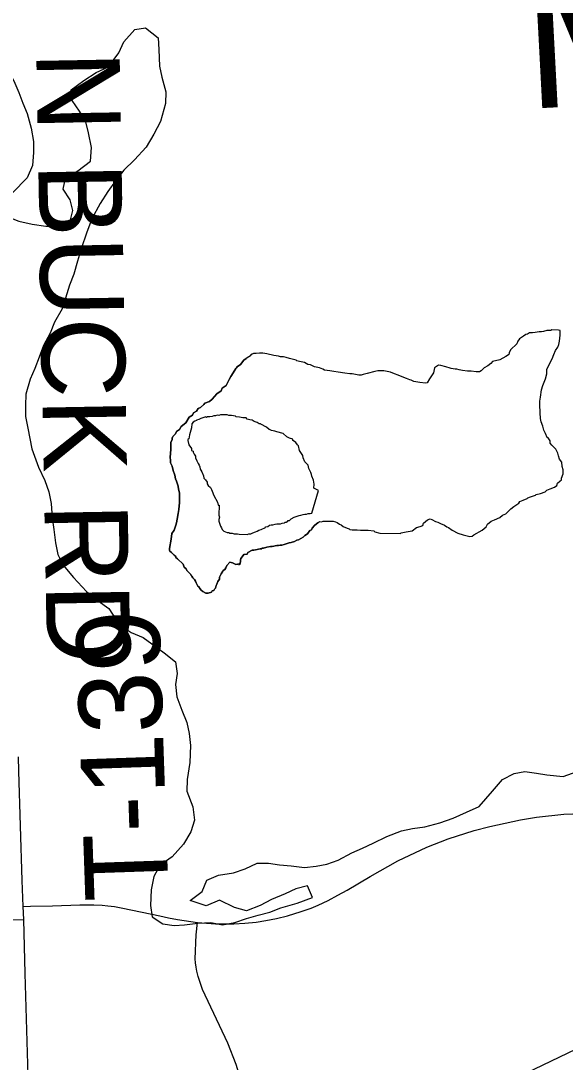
# Model space of a CAD drawing. Extents: x 63.4 to 97.4, y 0.4 to 22.4.
# Drawn here: x 69.568 to 69.939, y 18.671 to 19.381 of the extents above; entities that cross this region are included whole.
import ezdxf

# ---------------------------------------------------------------- set-up
doc = ezdxf.new("R2010")
doc.units = 0
for name, color, linetype in [('GM_X_Minor_River', 7, 'Continuous'), ('GM_X_Minor_River_Text', 7, 'Continuous'), ('GM_X_State_Route', 7, 'Continuous'), ('GM_X_Township_Road', 7, 'Continuous'), ('GM_X_Township_Road_Text', 7, 'Continuous')]:
    doc.layers.add(name, color=color, linetype=linetype)

msp = doc.modelspace()

# ---------------------------------------------------------------- linework, layer by layer
at = {"layer": 'GM_X_Minor_River'}
for points in [[(69.55778, 19.38334), (69.55402, 19.3761), (69.55179, 19.36658), (69.55449, 19.35861), (69.55834, 19.34912), (69.56332, 19.3404), (69.56678, 19.33243), (69.56947, 19.32522), (69.57255, 19.31801), (69.57526, 19.30813), (69.57682, 19.29901), (69.57686, 19.29141), (69.57615, 19.28266), (69.57239, 19.27427), (69.56258, 19.26396), (69.55313, 19.25555), (69.55924, 19.24759), (69.56685, 19.24459), (69.57597, 19.24273), (69.58509, 19.24125)], [(69.58509, 19.24125), (69.59459, 19.24129), (69.60178, 19.24475), (69.60364, 19.25198), (69.60171, 19.2592), (69.59711, 19.2664), (69.59859, 19.27401), (69.60692, 19.279), (69.61562, 19.2855), (69.61633, 19.29501), (69.61438, 19.30489), (69.61244, 19.31249), (69.60823, 19.31969), (69.60325, 19.3269), (69.60246, 19.33412), (69.61116, 19.34062), (69.61948, 19.34599), (69.62781, 19.34983), (69.63498, 19.35937), (69.63836, 19.36699), (69.64591, 19.37539), (69.65311, 19.37657), (69.66188, 19.36976), (69.6623, 19.36178), (69.66274, 19.35037), (69.6643, 19.34277), (69.66701, 19.3329), (69.66667, 19.32491), (69.66331, 19.31273), (69.6588, 19.30396), (69.65353, 19.29519), (69.64561, 19.28641), (69.63843, 19.27953), (69.63277, 19.27227), (69.62749, 19.26502), (69.62222, 19.25663), (69.61658, 19.24634), (69.61283, 19.23644), (69.60947, 19.22653), (69.60686, 19.21739), (69.60425, 19.20864), (69.60125, 19.20102), (69.59863, 19.19226), (69.59639, 19.18502), (69.59113, 19.17587), (69.58813, 19.16825), (69.58362, 19.15987), (69.58062, 19.15187), (69.57762, 19.14425), (69.57462, 19.13701), (69.57164, 19.12673), (69.5713, 19.11912), (69.57134, 19.11151), (69.5729, 19.10354), (69.57563, 19.08948), (69.58025, 19.07695), (69.58447, 19.06785), (69.58717, 19.06025), (69.58873, 19.05228), (69.58954, 19.04239), (69.59072, 19.03441), (69.5919, 19.0253), (69.59346, 19.01732), (69.59692, 19.01011), (69.60417, 19.00178), (69.61295, 18.99231), (69.62096, 18.98589), (69.6282, 18.9806), (69.63509, 18.9696), (69.64347, 18.96432), (69.65146, 18.96093), (69.66594, 18.95036), (69.67357, 18.94431), (69.67475, 18.93633), (69.67365, 18.92872), (69.67445, 18.92036), (69.67791, 18.91125), (69.68138, 18.9029), (69.68293, 18.8953), (69.68373, 18.88732), (69.68341, 18.87553), (69.68158, 18.86412), (69.68123, 18.85613), (69.68547, 18.84551), (69.68665, 18.83639), (69.68404, 18.82839), (69.67914, 18.82), (69.67122, 18.81122), (69.66289, 18.80548), (69.65876, 18.79785), (69.6569, 18.78872), (69.65658, 18.77807), (69.65776, 18.77047), (69.665, 18.76556), (69.6726, 18.76446), (69.67981, 18.76487), (69.68891, 18.76606), (69.69764, 18.76648), (69.70563, 18.76499), (69.71397, 18.76655), (69.72193, 18.76925)], [(69.93029, 19.1508), (69.93147, 19.15382), (69.93265, 19.15646), (69.9342, 19.15872), (69.93498, 19.16061), (69.93539, 19.16289), (69.93584, 19.16706), (69.93588, 19.1701), (69.93475, 19.17049), (69.9302, 19.17056), (69.92943, 19.17019), (69.92678, 19.17023), (69.9245, 19.1695), (69.92297, 19.16914), (69.92146, 19.16916), (69.9188, 19.16882), (69.9169, 19.16847), (69.915, 19.16849), (69.91347, 19.16776), (69.91233, 19.16739), (69.9108, 19.16627), (69.90812, 19.16441), (69.90696, 19.16291), (69.90617, 19.16102), (69.90194, 19.1569), (69.90115, 19.15501), (69.90076, 19.15388), (69.89999, 19.15313), (69.89884, 19.15239), (69.89464, 19.15016), (69.88969, 19.14909), (69.88853, 19.14759), (69.88661, 19.1461), (69.88394, 19.14462), (69.88201, 19.14274), (69.88087, 19.142), (69.87859, 19.14203), (69.87518, 19.14246), (69.87253, 19.1425), (69.86912, 19.14293), (69.86685, 19.14334), (69.86534, 19.14374), (69.86421, 19.14376), (69.86156, 19.14417), (69.86081, 19.14456), (69.85778, 19.14537), (69.85438, 19.14618), (69.85287, 19.14658), (69.85019, 19.14472), (69.84938, 19.14131), (69.84667, 19.13716), (69.84511, 19.13453), (69.84397, 19.13416), (69.84018, 19.1346), (69.83602, 19.13542), (69.83414, 19.1362), (69.83339, 19.13659), (69.83112, 19.13738), (69.82811, 19.13857), (69.82547, 19.13975), (69.82283, 19.14054), (69.82019, 19.14172), (69.81565, 19.14255), (69.81148, 19.1426), (69.80958, 19.14225), (69.80425, 19.14081), (69.80159, 19.14008), (69.80006, 19.13973), (69.79855, 19.13975), (69.79401, 19.14057), (69.79249, 19.14059), (69.78909, 19.14102), (69.78455, 19.14184), (69.78152, 19.14227), (69.77887, 19.14269), (69.77509, 19.14312), (69.77396, 19.14389), (69.7717, 19.14469), (69.7683, 19.14549), (69.76566, 19.14667), (69.76377, 19.14708), (69.76151, 19.14825), (69.75811, 19.14906), (69.75622, 19.14946), (69.75585, 19.14985), (69.75131, 19.15105), (69.74905, 19.15184), (69.74716, 19.15225), (69.74526, 19.15228), (69.74375, 19.15268), (69.74073, 19.1531), (69.73581, 19.15431), (69.73317, 19.15473), (69.73089, 19.15476), (69.72861, 19.15441), (69.72672, 19.15444), (69.72595, 19.15407), (69.7248, 19.15333), (69.7248, 19.15295), (69.72365, 19.1522), (69.72174, 19.15109)], [(69.72174, 19.15109), (69.7202, 19.14997), (69.71788, 19.14697), (69.71559, 19.14548), (69.7152, 19.14472), (69.71481, 19.14435), (69.71404, 19.14322), (69.71132, 19.1387), (69.71015, 19.13682), (69.7082, 19.13266), (69.70551, 19.1308), (69.70473, 19.12891), (69.70167, 19.12706), (69.69858, 19.1233), (69.69666, 19.12181), (69.69361, 19.12071), (69.69284, 19.11959), (69.69053, 19.11772), (69.68901, 19.11698), (69.68784, 19.1151), (69.68593, 19.11398), (69.68515, 19.11248), (69.68285, 19.11099), (69.68052, 19.10722), (69.67745, 19.10461), (69.67628, 19.10272), (69.67437, 19.10123), (69.67359, 19.09972), (69.67205, 19.09822), (69.67165, 19.09709), (69.67127, 19.09709), (69.67126, 19.09595), (69.67046, 19.09369), (69.6704, 19.08913), (69.66994, 19.08381), (69.67029, 19.08153), (69.67026, 19.08001), (69.67137, 19.07772), (69.67208, 19.07467), (69.67317, 19.07161), (69.67352, 19.06895), (69.67425, 19.06742), (69.67534, 19.06398), (69.67569, 19.06208), (69.67641, 19.05941), (69.67631, 19.05295), (69.67586, 19.04802), (69.67545, 19.04536), (69.67463, 19.04158), (69.67421, 19.03892), (69.67381, 19.03741), (69.67263, 19.03401), (69.67107, 19.03175), (69.67064, 19.02796), (69.66941, 19.02151), (69.66939, 19.02037), (69.66976, 19.01961), (69.67089, 19.01883), (69.67275, 19.01691), (69.67388, 19.01613), (69.67387, 19.01537), (69.67499, 19.01459), (69.67873, 19.01074), (69.67946, 19.00884), (69.68096, 19.00767), (69.68132, 19.00653), (69.68394, 19.00383), (69.68431, 19.00307), (69.68468, 19.00268), (69.68542, 19.00153), (69.68654, 19.00037), (69.68728, 18.99923), (69.68765, 18.99808), (69.68875, 18.99579), (69.6895, 18.9954), (69.68987, 18.99463), (69.69024, 18.99425), (69.69099, 18.99309), (69.69211, 18.99232), (69.69437, 18.99115), (69.69589, 18.99112), (69.69817, 18.99185), (69.69856, 18.99261), (69.69971, 18.99297), (69.7001, 18.99373), (69.70087, 18.99448), (69.70127, 18.99637), (69.70166, 18.99712), (69.70245, 18.99901), (69.70361, 19.00051), (69.70363, 19.00203), (69.7048, 19.0043), (69.70596, 19.00618), (69.70597, 19.00656), (69.70712, 19.0073), (69.70789, 19.00843), (69.70867, 19.00994), (69.7106, 19.01219), (69.71249, 19.01179), (69.71475, 19.01062), (69.7175, 19.01103)], [(69.71703, 19.01096), (69.71475, 19.01062), (69.71249, 19.01179), (69.7106, 19.01219), (69.70867, 19.00994), (69.70789, 19.00843), (69.70712, 19.0073), (69.70597, 19.00656), (69.70596, 19.00618), (69.7048, 19.0043), (69.70363, 19.00203), (69.70361, 19.00051), (69.70245, 18.99901), (69.70166, 18.99712), (69.70127, 18.99637), (69.70087, 18.99448), (69.7001, 18.99373), (69.69971, 18.99297), (69.69856, 18.99261), (69.69817, 18.99185), (69.69589, 18.99112), (69.69437, 18.99115), (69.69211, 18.99232), (69.69099, 18.99309), (69.69024, 18.99425), (69.68987, 18.99463), (69.6895, 18.9954), (69.68875, 18.99579), (69.68765, 18.99808), (69.68728, 18.99923), (69.68654, 19.00037), (69.68542, 19.00153), (69.68468, 19.00268), (69.68431, 19.00307), (69.68394, 19.00383), (69.68132, 19.00653), (69.68096, 19.00767), (69.67946, 19.00884), (69.67873, 19.01074), (69.67499, 19.01459), (69.67387, 19.01537), (69.67388, 19.01613), (69.67275, 19.01691), (69.67089, 19.01883), (69.66976, 19.01961), (69.66939, 19.02037), (69.66941, 19.02151), (69.67064, 19.02796), (69.67107, 19.03175), (69.67263, 19.03401), (69.67381, 19.03741), (69.67421, 19.03892), (69.67463, 19.04158), (69.67545, 19.04536), (69.67586, 19.04802), (69.67631, 19.05295), (69.67641, 19.05941), (69.67569, 19.06208), (69.67534, 19.06398), (69.67425, 19.06742), (69.67352, 19.06895), (69.67317, 19.07161), (69.67208, 19.07467), (69.67137, 19.07772), (69.67026, 19.08001), (69.67029, 19.08153), (69.66994, 19.08381), (69.6704, 19.08913), (69.67046, 19.09369), (69.67126, 19.09595), (69.67127, 19.09709), (69.67165, 19.09709), (69.67205, 19.09822), (69.67359, 19.09972), (69.67437, 19.10123), (69.67628, 19.10272), (69.67745, 19.10461), (69.68052, 19.10722), (69.68285, 19.11099), (69.68515, 19.11248), (69.68593, 19.11398), (69.68784, 19.1151), (69.68901, 19.11698), (69.69053, 19.11772), (69.69284, 19.11959), (69.69361, 19.12071), (69.69666, 19.12181), (69.69858, 19.1233), (69.70167, 19.12706), (69.70473, 19.12891), (69.70551, 19.1308), (69.7082, 19.13266), (69.71015, 19.13682), (69.71132, 19.1387), (69.71404, 19.14322), (69.71481, 19.14435), (69.7152, 19.14472), (69.71559, 19.14548), (69.71788, 19.14697), (69.7202, 19.14997), (69.72174, 19.15109)], [(69.77053, 19.03908), (69.77168, 19.03982), (69.7732, 19.0398), (69.77434, 19.04017), (69.77623, 19.04014), (69.78116, 19.04007), (69.78267, 19.03967), (69.78381, 19.03927), (69.78531, 19.03811), (69.78644, 19.03772), (69.78794, 19.03655), (69.79057, 19.03538), (69.79208, 19.03498), (69.79246, 19.03459), (69.79397, 19.03419), (69.79738, 19.03414), (69.79966, 19.03411), (69.80496, 19.03404), (69.80875, 19.0336), (69.80949, 19.03283), (69.8129, 19.03202), (69.82692, 19.03183), (69.82731, 19.0322), (69.83073, 19.03291), (69.83491, 19.03361), (69.83798, 19.03585), (69.84026, 19.03657), (69.84217, 19.03731), (69.84257, 19.03882), (69.84526, 19.04106), (69.84717, 19.0418), (69.8483, 19.0414), (69.85093, 19.03984), (69.85244, 19.03944), (69.85433, 19.03866), (69.85696, 19.03748), (69.85846, 19.03632), (69.85959, 19.03592), (69.86222, 19.03398), (69.86598, 19.03203), (69.86976, 19.03084), (69.87429, 19.02963), (69.87581, 19.02999), (69.87696, 19.03074), (69.8827, 19.03407), (69.88539, 19.03632), (69.88617, 19.0382), (69.88885, 19.04007), (69.89114, 19.04117), (69.89458, 19.04265), (69.8965, 19.04414), (69.89879, 19.04524), (69.90225, 19.04862), (69.90417, 19.05011), (69.90761, 19.05234), (69.90839, 19.05347), (69.91068, 19.05457), (69.91335, 19.05568), (69.91373, 19.05605), (69.91564, 19.05678), (69.91907, 19.05787), (69.91945, 19.05825), (69.9225, 19.05897), (69.92555, 19.06006), (69.9267, 19.06119), (69.92899, 19.06229), (69.93204, 19.06339), (69.93358, 19.06451), (69.93398, 19.06602), (69.93552, 19.06752), (69.93666, 19.06826), (69.93668, 19.06941), (69.93786, 19.07243), (69.9379, 19.07509), (69.93718, 19.07737), (69.93684, 19.08042), (69.93535, 19.08234), (69.93463, 19.08463), (69.93428, 19.08653), (69.9328, 19.08921), (69.93018, 19.09191), (69.92907, 19.09345), (69.92909, 19.09497), (69.9276, 19.09689), (69.92685, 19.09728), (69.92575, 19.09995), (69.92465, 19.10225), (69.92393, 19.10492), (69.92284, 19.10797), (69.92249, 19.11026), (69.92217, 19.11406), (69.92187, 19.11976), (69.92191, 19.12204), (69.92232, 19.1247), (69.92315, 19.12962), (69.92395, 19.13265), (69.92592, 19.13718), (69.92673, 19.14059), (69.92677, 19.14363), (69.92834, 19.14703), (69.93029, 19.1508)], [(69.77108, 19.06115), (69.76798, 19.06276), (69.76801, 19.06542), (69.76767, 19.06809), (69.76657, 19.07076), (69.76621, 19.07191), (69.76586, 19.07343), (69.76438, 19.07611), (69.76403, 19.0784), (69.76179, 19.08071), (69.76069, 19.08338), (69.76034, 19.08491), (69.75811, 19.08836), (69.7574, 19.09141), (69.75665, 19.09218), (69.75553, 19.09371), (69.75479, 19.09448), (69.75366, 19.09526), (69.75367, 19.09602), (69.75141, 19.09681), (69.74952, 19.0976), (69.74691, 19.09992), (69.74275, 19.10111), (69.74124, 19.10151), (69.73897, 19.10193), (69.73822, 19.10232), (69.73746, 19.10271), (69.73559, 19.10425), (69.73183, 19.10621), (69.73145, 19.10659), (69.7307, 19.1066), (69.72919, 19.10738), (69.72731, 19.10817), (69.7258, 19.10895), (69.72429, 19.10935), (69.7224, 19.10976), (69.72165, 19.11053), (69.71938, 19.11056), (69.71711, 19.11098), (69.71484, 19.11139), (69.71447, 19.11177), (69.71182, 19.11219), (69.70992, 19.11222), (69.70879, 19.11261), (69.70424, 19.11268), (69.7031, 19.11231), (69.70196, 19.11233), (69.70082, 19.11197), (69.69968, 19.11198), (69.69854, 19.11162), (69.69702, 19.11126), (69.6955, 19.11128), (69.69474, 19.11091), (69.69436, 19.1113), (69.69093, 19.1102), (69.68941, 19.10947), (69.68788, 19.10911), (69.68788, 19.10873), (69.68674, 19.10837), (69.68559, 19.10762), (69.68481, 19.10649), (69.6844, 19.10384), (69.68319, 19.09891), (69.68277, 19.09626), (69.682, 19.09589), (69.68199, 19.09513), (69.68271, 19.09209), (69.68457, 19.08978), (69.68455, 19.08826), (69.68568, 19.08786), (69.68567, 19.0871), (69.68641, 19.08595), (69.68714, 19.08442), (69.68713, 19.08328), (69.68824, 19.08137), (69.68897, 19.07946), (69.68971, 19.07831), (69.69007, 19.07716), (69.69043, 19.07564), (69.6908, 19.07487), (69.69154, 19.07372), (69.69264, 19.07105), (69.69299, 19.06952), (69.69411, 19.06837), (69.69523, 19.06683), (69.69521, 19.06569), (69.69595, 19.06454), (69.69745, 19.063), (69.69819, 19.06185), (69.69855, 19.06071), (69.69964, 19.05765), (69.70223, 19.05305), (69.70258, 19.05115), (69.70334, 19.05114), (69.70324, 19.0443), (69.7036, 19.04278), (69.7032, 19.04126), (69.70318, 19.04012)], [(69.70318, 19.04012), (69.70427, 19.03669), (69.70501, 19.03554), (69.70537, 19.03439), (69.70649, 19.03324), (69.70876, 19.03245), (69.70989, 19.03243), (69.71065, 19.03204), (69.71216, 19.03202), (69.71367, 19.03162), (69.71595, 19.03159), (69.71708, 19.03119), (69.72239, 19.03111), (69.72353, 19.03148), (69.72505, 19.03146), (69.7262, 19.0322), (69.7281, 19.03293), (69.72925, 19.0333), (69.73039, 19.03404), (69.73191, 19.0344), (69.73497, 19.03588), (69.73498, 19.03626), (69.7365, 19.03661), (69.73765, 19.03736), (69.73879, 19.03772), (69.73993, 19.0377), (69.74145, 19.03806), (69.74259, 19.03843), (69.74524, 19.03839), (69.74639, 19.03875), (69.74791, 19.03911), (69.7483, 19.03949), (69.74906, 19.03948), (69.7502, 19.04022), (69.75021, 19.0406), (69.75134, 19.04058), (69.7525, 19.04171), (69.75441, 19.04282), (69.75784, 19.04391), (69.75898, 19.04427), (69.76051, 19.04463), (69.76165, 19.045), (69.76279, 19.04498), (69.76393, 19.04534), (69.76545, 19.04532), (69.76659, 19.04569), (69.77108, 19.06115)], [(69.77053, 19.03908), (69.76976, 19.03833), (69.76823, 19.03721), (69.76668, 19.03534), (69.76629, 19.0342), (69.76515, 19.03384), (69.76359, 19.03158), (69.76168, 19.03047), (69.76053, 19.02934), (69.759, 19.02823), (69.75747, 19.02749), (69.75632, 19.02712), (69.7548, 19.02639), (69.75251, 19.02566), (69.75099, 19.0253), (69.74756, 19.02421), (69.74604, 19.02385), (69.7449, 19.02387), (69.74376, 19.0235), (69.74262, 19.02352), (69.73958, 19.0228), (69.73844, 19.02282), (69.73578, 19.02248), (69.73349, 19.02175), (69.73236, 19.02176), (69.73235, 19.02138), (69.73121, 19.0214), (69.72817, 19.02068), (69.72703, 19.02032), (69.72589, 19.02034), (69.72284, 19.01886), (69.72244, 19.01773), (69.72016, 19.01738), (69.719, 19.01587), (69.71823, 19.01474), (69.71783, 19.01361), (69.71781, 19.01247), (69.71741, 19.01058), (69.71664, 19.01021)], [(69.7175, 19.01103), (69.71781, 19.01247), (69.71783, 19.01361), (69.71823, 19.01474), (69.719, 19.01587), (69.72016, 19.01738), (69.72244, 19.01773), (69.72284, 19.01886), (69.72589, 19.02034), (69.72703, 19.02032), (69.72817, 19.02068), (69.73121, 19.0214), (69.73235, 19.02138), (69.73236, 19.02176), (69.73349, 19.02175), (69.73578, 19.02248), (69.73844, 19.02282), (69.73958, 19.0228), (69.74262, 19.02352), (69.74376, 19.0235), (69.7449, 19.02387), (69.74604, 19.02385), (69.74756, 19.02421), (69.75099, 19.0253), (69.75251, 19.02566), (69.7548, 19.02639), (69.75632, 19.02712), (69.75747, 19.02749), (69.759, 19.02823), (69.76053, 19.02934), (69.76168, 19.03047), (69.76359, 19.03158), (69.76515, 19.03384), (69.76629, 19.0342), (69.76668, 19.03534), (69.76823, 19.03721), (69.76976, 19.03833), (69.77053, 19.03908)], [(69.72193, 18.76925), (69.72989, 18.77157), (69.73785, 18.77351), (69.74543, 18.77659), (69.75642, 18.77968), (69.76703, 18.78353), (69.76357, 18.7915), (69.75561, 18.78956), (69.74842, 18.78611), (69.73895, 18.78226), (69.73137, 18.77804), (69.7219, 18.77458), (69.71391, 18.77682), (69.70364, 18.78171), (69.69455, 18.77787), (69.68352, 18.78162), (69.69184, 18.78774), (69.69484, 18.79536), (69.70279, 18.79882), (69.71303, 18.80039), (69.72099, 18.80309), (69.72933, 18.80693), (69.73692, 18.80697), (69.74452, 18.80586), (69.7525, 18.80514), (69.76161, 18.80404), (69.76958, 18.80484), (69.77679, 18.80639), (69.78437, 18.80909), (69.79383, 18.81408), (69.80103, 18.81715), (69.80823, 18.82061), (69.81769, 18.82522), (69.82755, 18.82906), (69.83513, 18.83062), (69.84348, 18.8318), (69.85371, 18.83451), (69.86281, 18.83759), (69.8719, 18.84182), (69.88061, 18.84566), (69.88967, 18.85597), (69.89646, 18.86399), (69.90441, 18.86821), (69.91163, 18.86938), (69.9196, 18.86828), (69.92682, 18.86717), (69.93784, 18.86608), (69.94731, 18.86955)]]:
    msp.add_lwpolyline(points, dxfattribs=at)
at = {"layer": 'GM_X_State_Route'}
msp.add_lwpolyline([(69.58254, 18.36366), (69.58148, 18.39235), (69.57927, 18.46566), (69.57766, 18.51493), (69.57605, 18.562), (69.57547, 18.5819), (69.57504, 18.59625), (69.57384, 18.63911), (69.57102, 18.73185), (69.5701, 18.76869), (69.56979, 18.77749)], dxfattribs=at)
at = {"layer": 'GM_X_Township_Road'}
msp.add_line((69.53758, 18.76803), (69.5701, 18.76869), dxfattribs=at)
for points in [[(69.56979, 18.77749), (69.56916, 18.79508), (69.56679, 18.8697), (69.56652, 18.8795)], [(69.6885, 18.76643), (69.7009, 18.76553), (69.71334, 18.7657), (69.72096, 18.76601), (69.72856, 18.76683), (69.73515, 18.76786), (69.74235, 18.7693), (69.74995, 18.77115), (69.75918, 18.77396), (69.76618, 18.77639), (69.77082, 18.77835), (69.77763, 18.78163), (69.78429, 18.78512), (69.7905, 18.78862), (69.80623, 18.79785), (69.82524, 18.80847), (69.8449, 18.81787), (69.85936, 18.8236), (69.87718, 18.82916), (69.88795, 18.83192), (69.89836, 18.83427), (69.90868, 18.83644), (69.91977, 18.83824), (69.93833, 18.84031), (69.95697, 18.84109)], [(69.56979, 18.77749), (69.57486, 18.77761), (69.58971, 18.77795), (69.6084, 18.77867), (69.6179, 18.77868), (69.62358, 18.77845), (69.62751, 18.77801), (69.63209, 18.77735), (69.63766, 18.77637), (69.66286, 18.77104), (69.66886, 18.76972), (69.67486, 18.76852), (69.6885, 18.76643)], [(69.72737, 18.59575), (69.72479, 18.625), (69.7234, 18.63578), (69.72136, 18.64666), (69.71858, 18.65779), (69.71501, 18.6697), (69.70933, 18.68421), (69.69194, 18.72079), (69.689, 18.72965), (69.68818, 18.73329), (69.68774, 18.73601), (69.68731, 18.73896), (69.68708, 18.74169), (69.68719, 18.74693), (69.68741, 18.75282), (69.68774, 18.75816), (69.6885, 18.76643)], [(69.72737, 18.59575), (69.74326, 18.59646), (69.75868, 18.59822), (69.77392, 18.60118), (69.78582, 18.60468), (69.79731, 18.60937), (69.85074, 18.63427), (69.95792, 18.68559)]]:
    msp.add_lwpolyline(points, dxfattribs=at)

# ---------------------------------------------------------------- texts
at = {"layer": 'GM_X_Minor_River_Text'}
msp.add_text('Middle', height=0.094758, rotation=3.00858, dxfattribs=at).set_placement((69.91323, 19.32125))
at = {"layer": 'GM_X_Township_Road_Text'}
for s, rotation, p in [('N BUCK RD', 271.01966, (69.57865, 19.36019)), ('T-139', 91.95428, (69.66897, 18.78221))]:
    msp.add_text(s, height=0.056818, rotation=rotation, dxfattribs=at).set_placement(p)

doc.saveas('drawing.dxf')
